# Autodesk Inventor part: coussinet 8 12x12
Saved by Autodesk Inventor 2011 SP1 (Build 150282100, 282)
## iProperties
Created: 2010-12
Part Number: coussinet 8 12x12
Document SubType Name: Modeling
Designer: eric
Density: 1 g/cm^3
Mass: 0.748327 g
Surface Area: 8.57562 cm^2
Volume: 0.748327 cm^3
Author: eric
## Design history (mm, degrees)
feature "Base1"
node "Solide1"
node "Corps solides"
node "Corps surfaciques"
